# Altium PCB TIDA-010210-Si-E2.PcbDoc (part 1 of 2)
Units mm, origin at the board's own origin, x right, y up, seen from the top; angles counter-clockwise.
Board outline 75 x 60 mm, 2 copper layers (Top Layer, Bottom Layer), stack 1.565 mm thick; 77 components, 33 nets, 164 pads, 32 vias.
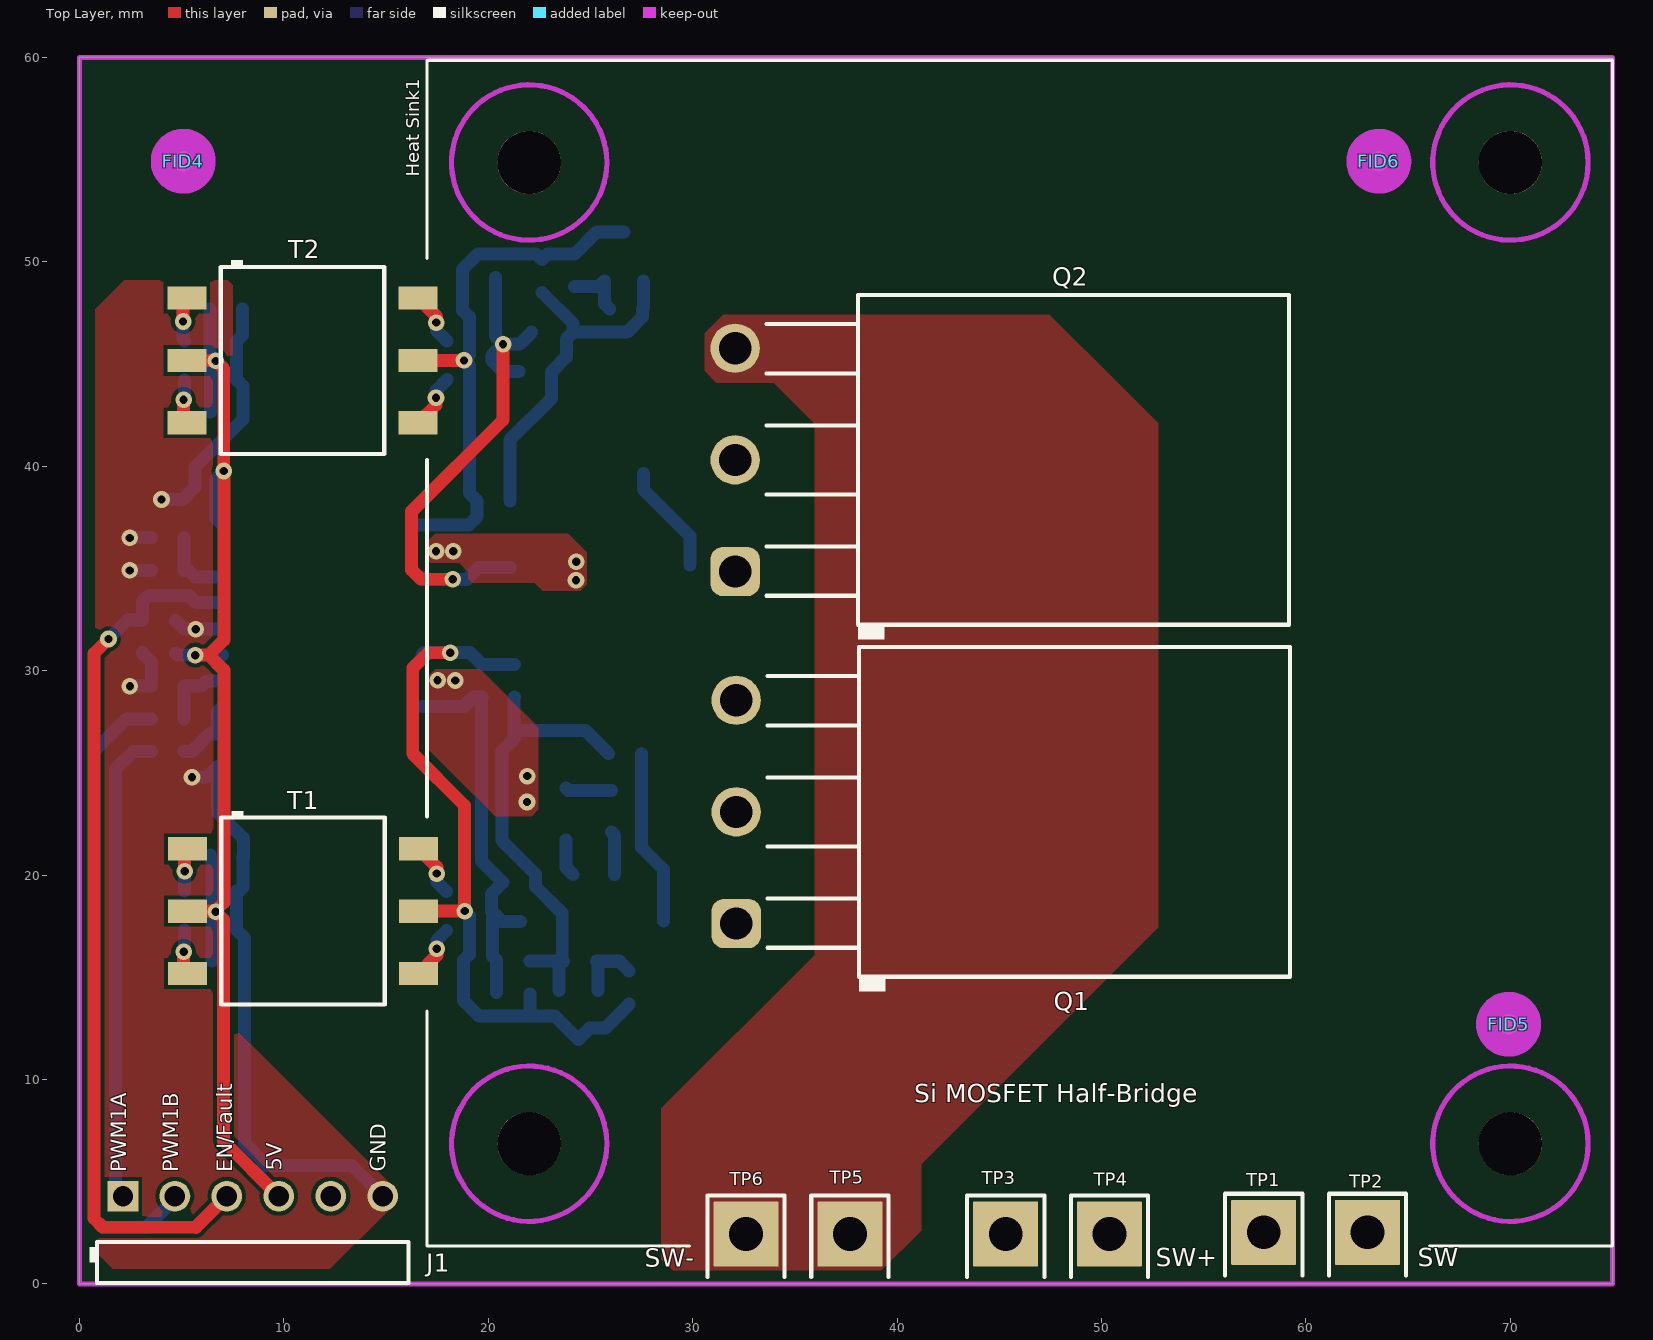
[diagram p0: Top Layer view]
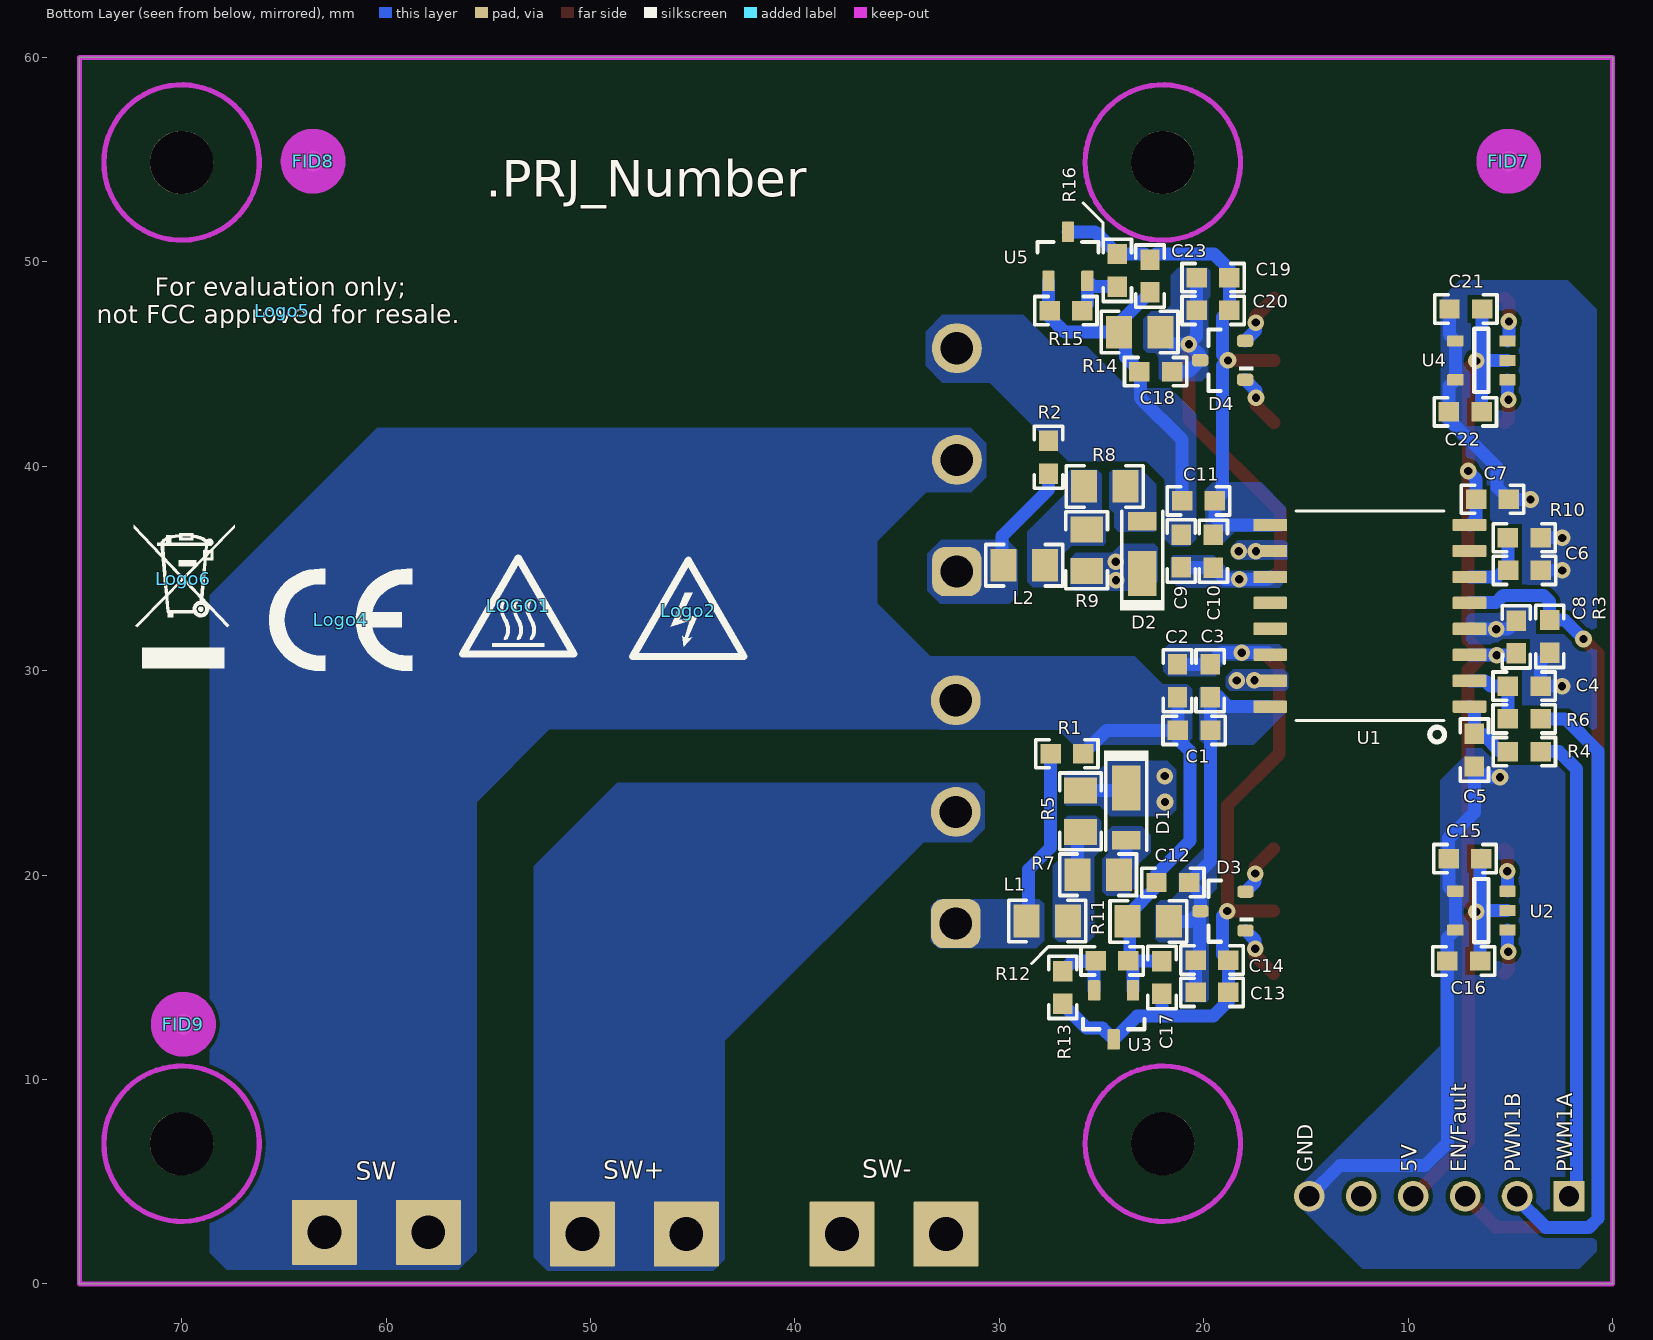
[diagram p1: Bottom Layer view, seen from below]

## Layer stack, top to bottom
Top Solder: solder mask 0.0102, Solder Resist, Dk 3.5
Top Layer: signal copper 0.0711
Dielectric 1: core 1.4224, FR-4 High Tg, Dk 4.2
Bottom Layer: signal copper 0.0711
Bottom Solder: solder mask 0.0102, Solder Resist, Dk 3.5

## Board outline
0,0 0,60 75,60 75,0

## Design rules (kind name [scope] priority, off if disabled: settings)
AcuteAngle [All] p1: minimum=4.50000000000000E+0001 checktracksonly=FALSE
AssemblyTestPointUsage [All] p1: valid=2
BoardOutlineClearance BoardOutlineClearance_MountingHoles [OnCopper and InComponentClass('Mounting Holes')] p1: gap=0.762 ignorepadtopadclearanceinfootprint=FALSE
BoardOutlineClearance BoardOutlineClearance_Poly [OnCopper and InPoly] p2: gap=0.635 ignorepadtopadclearanceinfootprint=FALSE
BoardOutlineClearance [OnCopper and Not InComponentClass('Logo') and not InComponentClass('FiducialMark') and not InRegion(1000,500,4000,800)] p3: gap=0.381 ignorepadtopadclearanceinfootprint=FALSE
Clearance Clearance_1 [All] p1: gap=0.2 ignorepadtopadclearanceinfootprint=FALSE except(0: Arc-SMDPad Arc-THPad Arc-Hole Track-Hole SMDPad-Hole THPad-Hole Via-Hole Fill-Hole Poly-Hole Region-Hole Text-Hole)
Clearance Clearance_Poly_poly [InPoly vs InPoly] p2: gap=0.508 ignorepadtopadclearanceinfootprint=FALSE except(0: Arc-Hole Track-Hole SMDPad-Hole THPad-Hole Via-Hole Fill-Hole Poly-Hole Region-Hole Text-Hole)
Clearance Clearance_Keepouts [((IsTrack Or IsArc) And Not InPoly) And IsFree and IsKeepOut vs ((IsTrack Or IsArc) And Not InPoly) And IsFree and IsKeepOut] p3: gap=0.508 ignorepadtopadclearanceinfootprint=FALSE except(0: Arc-Hole Track-Hole SMDPad-Hole THPad-Hole Via-Hole Fill-Hole Poly-Hole Region-Hole Text-Hole)
Clearance Clearance_Poly [InPolygon] p4: gap=0.381 ignorepadtopadclearanceinfootprint=FALSE except(0: Arc-Hole Track-Hole SMDPad-Hole THPad-Hole Via-Hole Fill-Hole Poly-Hole Region-Hole Text-Hole)
Clearance Clearance_2 [All] p5: gap=2.54 ignorepadtopadclearanceinfootprint=FALSE except(0: Arc-SMDPad Arc-THPad Arc-Hole Track-Hole SMDPad-Hole THPad-Hole Via-Hole Fill-Hole Poly-Hole Region-Hole Text-Hole; 0.254: Arc-Arc Arc-Track Arc-Via Arc-Fill Arc-Poly Arc-Region Arc-Text)
ComponentClearance ComponentClearance_MountingHoles_FiducialMarks [InComponentClass('Mounting Holes') vs InComponentClass('FiducialMark')] p1: gap=0.254 collisioncheckmode=3 verticalgap=0.254 showdistances=FALSE
ComponentClearance ComponentClearance_Shunt [InComponentClass('Header') vs InComponentClass('Shunt')] p2: gap=0 collisioncheckmode=3 verticalgap=0 showdistances=FALSE
ComponentClearance ComponentClearance_Logo [InComponentClass('Logo')] p3: gap=0.127 collisioncheckmode=3 verticalgap=0.127 showdistances=FALSE
ComponentClearance ComponentClearance_ScrewToNut [(HasFootprint('NY PMS 440 0025 PH')) vs (HasFootprint('Keystone_1902C'))] p4: gap=0.127 collisioncheckmode=3 verticalgap=0.254 showdistances=FALSE
ComponentClearance ComponentClearance_MountingHoles [InComponentClass('Mounting Holes')] p5: gap=6.35 collisioncheckmode=3 verticalgap=2540 showdistances=FALSE
ComponentClearance ComponentClearance_SmallPassives [HasFootprint('0201*') or HasFootprint('0402*') or HasFootprint('0508') or HasFootprint('0603*') or HasFootprint('0612') or HasFootprint('0805*') or HasFootprint('0815*') or HasFootprint('0830*') or HasFootprint('1206*') or HasFootprint('1210*') or HasFootprint('1808*') or HasFootprint('1812*') or HasFootprint('1825*') or HasFootprint('2010*') or HasFootprint('2220*') or HasFootprint('2225*') or HasFootprint('2512*') or HasFootprint('2728*') or HasFootprint('3518*') vs HasFootprint('0201*') or HasFootprint('0402*') or HasFootprint('0508') or HasFootprint('0603*') or HasFootprint('0612') or HasFootprint('0805*') or HasFootprint('0815*') or HasFootprint('0830*') or HasFootprint('1206*') or HasFootprint('1210*') or HasFootprint('1808*') or HasFootprint('1812*') or HasFootprint('1825*') or HasFootprint('2010*') or HasFootprint('2220*') or HasFootprint('2225*') or HasFootprint('2512*') or HasFootprint('2728*') or HasFootprint('3518*')] p6: gap=0.127 collisioncheckmode=3 verticalgap=0.127 showdistances=FALSE
ComponentClearance ComponentClearance_THtoSMT [IsThruComponent vs IsSMTComponent] p7: gap=0.127 collisioncheckmode=3 verticalgap=0.127 showdistances=FALSE
ComponentClearance ComponentClearance_THtoTH [IsThruComponent vs IsThruComponent] p8: gap=0 collisioncheckmode=3 verticalgap=0.254 showdistances=FALSE
ComponentClearance [All] p9: gap=0.025 collisioncheckmode=3 verticalgap=0.025 showdistances=FALSE
DiffPairsRouting [All] p1: maxlimit=2.54 minlimit=0.254 mostfreqgap=0.254 toplayer_minwidth=0.381 toplayer_maxwidth=0.381 toplayer_prefwidth=0.381 bottomlayer_minwidth=0.381 bottomlayer_maxwidth=0.381 bottomlayer_prefwidth=0.381 maxuncoupledlength=25.4
FabricationTestPointUsage TestPointUsage [All] p1: valid=2 allowmultiple=FALSE
FabricationTestpoint Testpoint [All] p1: side=3 testpointundercomponent=TRUE minsize=1.016 maxsize=2.54 preferedsize=1.524 minholesize=0 maxholesize=1.016 preferedholesize=0.813 testpointgrid=0.025 allowsidetop=TRUE allowsidebottom=TRUE usegrid=TRUE gridtolerance=0
FanoutControl Fanout_LCC [IsLCC] p1: bgadir=Out bgaviamode=Centered fanoutstyle=Auto fanoutdirection=Alternating viagrid=0.025 // Fanout_LCC (Default Rule)
FanoutControl Fanout_BGA [IsBGA] p2: bgadir=Out bgaviamode=Centered fanoutstyle=Auto fanoutdirection=Alternating viagrid=0.025 // Fanout_BGA (Default Rule)
FanoutControl Fanout_Default [All] p4: bgadir=Out bgaviamode=Centered fanoutstyle=Auto fanoutdirection=Alternating viagrid=0.025 // Fanout_Default (Default Rule)
FanoutControl Fanout_Small [(CompPinCount < 5)] p5: bgadir=Out bgaviamode=Centered fanoutstyle=Auto fanoutdirection=OutThenIn viagrid=0.025 // Fanout_Small (Default Rule)
Height [All] p1: minheight=0 maxheight=38.1 prefheight=12.7
HoleSize [All] p1: absolutevalues=TRUE maxlimit=6.375 minlimit=0.2 maxpercent=80.000 minpercent=20.000
MinimumAnnularRing MinimumAnnularRing_ThermalPadVias [IsVia and InAnyComponent] p1: minimumring=0.102
MinimumAnnularRing [All] p2: minimumring=0.102
MinimumSolderMaskSliver MinimumSolderMaskSliver_Logo [InComponentClass('Logo') vs InComponentClass('Logo')] p1: minsoldermaskwidth=0.018
MinimumSolderMaskSliver [All] p2: minsoldermaskwidth=0.1
PlaneClearance [All] p1: clearance=0.254
PlaneConnect [All] p1: planeconnectstyle=Relief reliefexpansion=0.254 reliefentries=4 reliefconductorwidth=0.254 reliefairgap=0.254
PolygonConnect PolygonConnectThermalVia [isvia] p1: connectstyle=Direct reliefconductorwidth=0.254 reliefentries=4 polygonreliefangle="90 Angle" airgapwidth=0.254
PolygonConnect PolygonConnectThermalPad [((ObjectKind = 'Pad') And (((Name Like 'U*') or (Name Like 'D*')) and (InComponentClass('TIDA-00183_pg-4_Driver') or InComponentClass('TIDA-00183_pg-5_OP_Connector')))) or ((ObjectKind = 'Pad') And (Name like 'U61*'))] p2: connectstyle=Direct reliefconductorwidth=0.254 reliefentries=4 polygonreliefangle="90 Angle" airgapwidth=0.254
PolygonConnect [All] p3: connectstyle=Direct reliefconductorwidth=0.254 reliefentries=4 polygonreliefangle="90 Angle" airgapwidth=0.127
RoutingVias ThermalPadVias [IsVia and InAnyComponent] p1: holewidth=0.2 width=0.5 viastyle="Through Hole" minholewidth=0.2 minwidth=0.5 maxholewidth=0.33 maxwidth=0.6
RoutingVias [All] p2: holewidth=0.406 width=0.864 viastyle="Through Hole" minholewidth=0.203 minwidth=0.508 maxholewidth=1.016 maxwidth=1.651
SilkToBoardRegionClearance [Not ((IsComment or IsDesignator) And (Hide <> 'False')) and not InRegion(1000,500,4000,800)] p1:
SilkToSilkClearance SilkToSilkClearance_Pb-FreeLogo [(HasFootprint('Pb-Free_Overlay_Medium') OR HasFootprint('Pb-Free_Overlay_Small')) vs (HasFootprint('Pb-Free_Overlay_Medium') OR HasFootprint('Pb-Free_Overlay_Small'))] p1: silktosilkclearance=0
SilkToSilkClearance [All] p2: silktosilkclearance=0.102
SilkToSolderMaskClearance SilkToComponentPadClearance [IsPad and InAnycomponent] p1: minsilkscreentomaskgap=0.127 clearancetoexposedcopper=TRUE
SilkToSolderMaskClearance "Silk to Solder Mask Opening" [All] p2: minsilkscreentomaskgap=0.102 clearancetoexposedcopper=FALSE
SolderMaskExpansion [All] p1: expansion=0.05 istentingtop=FALSE
Width [All] p1: maxlimit=2.54 minlimit=0.381 preferedwidth=0.635 toplayer_prefwidth=0.63 minimp=50.000000 maximp=50.000000 favimp=50.000000 checkconnectedcopper=TRUE
13 further rules are at their usual default settings.

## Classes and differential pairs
component class Header: J1
component class FiducialMark: FID4 FID5 FID6 FID7 FID8 FID9
component class "EVM Hardware-Pg6": FID4 FID5 FID6 FID7 FID8 FID9 J4 LOGO1 Logo2 Logo4 Logo5 Logo6 TP11 TP12 TP13 TP14 TP15 TP17 ZZ1 ZZ2 ZZ3 ZZ4
component class "Bias Power Supply-Pg5": C12 C13 C14 C15 C16 C17 C18 C19 C20 C21 C22 C23 C38 D3 D4 R11 R12 R13 R14 R15 R16 T1 T2 U2 U3 U4 U5
component class "Gate Driver Circuit-Pg4": C1 C2 C3 C4 C5 C6 C7 C8 C9 C10 C11 D1 D2 J1 L1 L2 R3 R4 R5 R6 R7 R8 R9 R10 U1
component class AssemblyNote: ZZ1 ZZ2 ZZ3 ZZ4
component class "Power Stage-Pg3": "Heat Sink1" Q1 Q2 R1 R2 TP1 TP2 TP3 TP4 TP5 TP6

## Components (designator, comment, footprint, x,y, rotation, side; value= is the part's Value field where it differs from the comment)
C1 "C1608X5R1V475K080AC" 0603 20.472,27.076 r0 bottom value=4.7uF
C2 "C1608X5R1V475K080AC" 0603 21.284,29.504 r270 bottom value=4.7uF
C3 "C1608X7R1H104K080AA" 0603 19.687,29.504 r90 bottom value=0.1uF
C4 "CL10B101KB8NNNC" 0603 4.327,29.238 r180 bottom value=100pF
C5 "CL10B101KB8NNNC" 0603 6.764,26.111 r270 bottom value=100pF
C6 "C0603X222K5RACTU" 0603 4.314,34.902 r180 bottom value=2200pF
C7 "C1608X7R1H104K080AA" 0603 5.877,38.382 r180 bottom value=0.1uF
C8 "C1608X7R1H104K080AA" 0603 4.711,31.651 r90 bottom value=0.1uF
C9 "C1608X5R1V475K080AC" 0603 21.1,35.854 r90 bottom value=4.7uF
C10 "C1608X7R1H104K080AA" 0603 19.534,35.842 r90 bottom value=0.1uF
C11 "C1608X5R1V475K080AC" 0603 20.259,38.305 r0 bottom value=4.7uF
C12 "C1608X7R1H104K080AA" 0603 21.514,19.634 r0 bottom value=0.1uF
C13 "C1608X5R1V475K080AC" 0603 19.601,14.26 r180 bottom value=4.7uF
C14 "C1608X5R1V475K080AC" 0603 19.601,15.84 r180 bottom value=4.7uF
C15 "GRM188Z71A106MA73D" 0603 7.219,20.801 r0 bottom value=10uF
C16 "GRM188Z71A106MA73D" 0603 7.283,15.797 r0 bottom value=10uF
C17 "C1608X7R1H104K080AA" 0603 22.047,14.986 r270 bottom value=0.1uF
C18 "C1608X7R1H104K080AA" 0603 22.352,44.628 r0 bottom value=0.1uF
C19 "C1608X5R1V475K080AC" 0603 19.545,49.225 r180 bottom value=4.7uF
C20 "C1608X5R1V475K080AC" 0603 19.545,47.625 r180 bottom value=4.7uF
C21 "GRM188Z71A106MA73D" 0603 7.181,47.691 r0 bottom value=10uF
C22 "GRM188Z71A106MA73D" 0603 7.206,42.661 r0 bottom value=10uF
C23 "C1608X7R1H104K080AA" 0603 22.631,49.301 r90 bottom value=0.1uF
D1 "DFLS240-7" PowerDI123 23.794,22.987 r270 bottom value=40V
D2 "DFLS240-7" PowerDI123 23.012,36.038 r90 bottom value=40V
D3 "BAV70-E3-08" SOT-23L 19.061,18.235 r0 bottom value=70V
D4 "BAV70-E3-08" SOT-23L 19.078,45.183 r0 bottom value=70V
FID4 "Fiducial" Fiducial10-30 5.08,54.92 r0 top
FID5 "Fiducial" Fiducial10-30 69.92,12.7 r0 top
FID6 "Fiducial" Fiducial10-30 63.57,54.92 r0 top
FID7 "Fiducial" Fiducial10-30 5.08,54.92 r180 bottom
FID8 "Fiducial" Fiducial10-30 63.57,54.92 r180 bottom
FID9 "Fiducial" Fiducial10-30 69.92,12.7 r180 bottom
"Heat Sink1" "SKV585811-AL" SKV585811_AL 46.005,30.858 r0 top locked
J1 "90121-0766" Molex_90121-0766 8.484,4.293 r0 top locked
L1 "782853121" 0805_HV 27.661,17.755 r0 bottom value="120 ohm"
L2 "782853121" 0805_HV 28.778,35.154 r0 bottom value="120 ohm"
LOGO1 "CAUTION HOT SURFACE" IEC_HotSurface_Small 53.54,33.17 r180 bottom
Logo2 "DANGER HIGH VOLTAGE" IEC_HighVoltage_Small 45.212,32.929 r180 bottom (schematic designator LOGO2)
Logo4 "CE Mark" CE_Mark_5mm 62.23,32.487 r180 bottom
Logo5 "FCC disclaimer" FCC_disclaimer_stacked 65.075,47.6 r0 bottom
Logo6 "WEEE logo" WEEE_Minimum 69.926,34.493 r180 bottom
Q1 "FCH040N65S3-F155" TO-247_HORIZONTAL_DOWN 32.131,23.089 r90 top locked value=650V
Q2 "FCH040N65S3-F155" TO-247_HORIZONTAL_DOWN 32.08,40.31 r90 top locked value=650V
R1 "CRCW060310K0JNEA" 0603 26.695,25.933 r0 bottom value=10k
R2 "CRCW060310K0JNEA" 0603 27.595,40.437 r270 bottom value=10k
R3 "RCA06031K00JNEA" 0603 3.076,31.676 r90 bottom value=1.0k
R4 "CRCW0603100RFKEA" 0603 4.321,26.037 r0 bottom value=100
R5 "CRCW080522R1FKEA" 0805_HV 26.03,23.114 r270 bottom value=22.1
R6 "CRCW0603100RFKEA" 0603 4.327,27.643 r0 bottom value=100
R7 "CRCW080522R1FKEA" 0805_HV 25.172,20.015 r0 bottom value=22.1
R8 "CRCW080522R1FKEA" 0805_HV 24.841,39.014 r0 bottom value=22.1
R9 "CRCW080522R1FKEA" 0805_HV 25.729,35.89 r90 bottom value=22.1
R10 "RT0603BRD0710KL" 0603 4.324,36.502 r0 bottom value=10.0k
R11 "CRCW08054K70JNEA" 0805_HV 22.708,17.735 r180 bottom value=4.7k
R12 "RT0603DRE074K99L" 0603 24.486,15.799 r180 bottom value=4.99k
R13 "RT0603DRE074K99L" 0603 26.899,14.503 r90 bottom value=4.99k
R14 "CRCW08054K70JNEA" 0805_HV 23.139,46.558 r180 bottom value=4.7k
R15 "RT0603DRE074K99L" 0603 26.745,47.614 r0 bottom value=4.99k
R16 "RT0603DRE074K99L" 0603 24.232,49.581 r270 bottom value=4.99k
T1 "750342879" Wurth_750342879 10.941,18.235 r0 top value=50uH
T2 "750342879" Wurth_750342879 10.914,45.176 r0 top value=50uH
TP1 "3620-2-32-15-00-00-08-0" Mill-Max_3620-2-32-xx-00-00-08-0 57.935,0 r0 top locked
TP2 "3620-2-32-15-00-00-08-0" Mill-Max_3620-2-32-xx-00-00-08-0 63.015,0 r0 top locked
TP3 "3620-2-32-15-00-00-08-0" Mill-Max_3620-2-32-xx-00-00-08-0 45.314,-0.082 r0 top locked
TP4 "3620-2-32-15-00-00-08-0" Mill-Max_3620-2-32-xx-00-00-08-0 50.394,-0.082 r0 top locked
TP5 "3620-2-32-15-00-00-08-0" Mill-Max_3620-2-32-xx-00-00-08-0 37.694,-0.082 r0 top locked
TP6 "3620-2-32-15-00-00-08-0" Mill-Max_3620-2-32-xx-00-00-08-0 32.614,-0.082 r0 top locked
U1 "UCC21540DWR" DW0016B_HV 11.876,32.679 r0 bottom
U2 "SN6501QDBVRQ1" DBV0005A_L 6.419,18.261 r0 bottom
U3 "ATL431LIAQDBZR" DBZ0003A_N 24.409,13.157 r270 bottom
U4 "SN6501QDBVRQ1" DBV0005A_L 6.419,45.176 r0 bottom
U5 "ATL431LIAQDBZR" DBZ0003A_N 26.645,50.267 r90 bottom
ZZ1 "This Assembly Note is for PCB labels only" AssemblyNoteLabel 5.186,73.84 r0 top
ZZ2 "This Assembly Note will show in the PcbDoc and associated outputs" AssemblyNote 5.186,71.074 r0 top
ZZ3 "This Assembly Note will show in the PcbDoc and associated outputs" AssemblyNote 5.186,68.825 r0 top
ZZ4 "This Assembly Note will show in the PcbDoc and associated outputs" AssemblyNote 5.186,66.575 r0 top

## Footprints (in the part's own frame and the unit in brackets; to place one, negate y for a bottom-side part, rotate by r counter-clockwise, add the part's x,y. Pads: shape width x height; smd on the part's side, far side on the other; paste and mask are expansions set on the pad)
0603 [mm] "0603 from SM-752 data"
  rect 1x0.95 smd: 1(-0.8,0) 2(0.8,0)
  silkscreen extent -1.52,-0.69 1.52,0.69, body extent -0.87,-0.47 0.87,0.47, height 1
0805_HV [mil] "0805 with 30mil clearance between pads"
  rect 50x63 smd: 1(-40,0) 2(40,0)
  silkscreen extent -74,-40 74,40, body extent -43,-29 43,29, height 57
AssemblyNote [mm] "Assembly Note"
AssemblyNoteLabel [mm] "Assembly Note for PCB Labels"
CE_Mark_5mm [mm] "Minimum text height for CE Mark"
  silkscreen extent -3.5,-2.5 3.5,2.5
DBV0005A_L [mm] "SOT23, 5-Leads, Body 2.9x1.6mm, Pitch 0.95mm, Lead Span 2.8mm, IPC High Density"
  rrect18% 0.8x0.55 smd: 1(-1.275,0.95) 2(-1.275,0) 3(-1.275,-0.95) 4(1.275,-0.95) 5(1.275,0.95)
  silkscreen extent -0.35,-1.55 0.35,1.55, body extent -1.42,-1.46 1.42,1.46, height 1.09
DBZ0003A_N [mm] "SOT23, 3-Leads, Body 2.9x1.3mm, Pitch 0.95mm, Lead Span 2.4mm, IPC Medium Density"
  rrect17% 1x0.6 smd: 1(-1.2,0.95) 2(-1.2,-0.95) 3(1.2,0)
  silkscreen extent 0.2,-1.5 0.7,1.5, body extent -1.26,-1.46 1.26,1.46, height 0.98
DW0016B_HV [mm] "SOIC-16, HV/isolation option"
  rrect17% 1.65x0.6 smd: 1(-4.875,4.445) 2(-4.875,3.175) 3(-4.875,1.905) 4(-4.875,0.635) 5(-4.875,-0.635) 6(-4.875,-1.905) 7(-4.875,-3.175) 8(-4.875,-4.445) 9(4.875,-4.445) 10(4.875,-3.175) 11(4.875,-1.905) 12(4.875,-0.635) 13(4.875,0.635) 14(4.875,1.905) 15(4.875,3.175) 16(4.875,4.445)
  body extent -5.17,-5.15 5.17,5.15, height 2.59
FCC_disclaimer_stacked [mm]
Fiducial10-30 [mm]
  round 1 smd mask+1: 1(0,0)
  Top Layer keep-out circle w1.678: c0,0 r0.75
IEC_HighVoltage_Small [mm]
  silkscreen extent -2.72,-2.24 2.72,2.47
IEC_HotSurface_Small [mm]
  silkscreen extent -2.72,-2.36 2.72,2.35
Mill-Max_3620-2-32-xx-00-00-08-0 [mm] "PCB Pin, 0.04\" DIA, R/A, Edge-Mount"
  rrect3% 3.18x3.18 hole 1.65: 1(0,2.52)
  silkscreen extent -1.89,0.41 1.89,4.41, body extent -1.59,-5.06 1.59,4.11, height 0.65
Molex_90121-0766 [mm] "Header, 2.54mm, 6x1, R/A, TH"
  rect 1.5x1.5 hole 1: 1(-6.35,0)
  round 1.5 hole 1: 2(-3.81,0) 3(-1.27,0) 4(1.27,0) 5(3.81,0) 6(6.35,0)
  silkscreen extent -8,-4.25 7.62,-2.25, body extent -7.62,-11 7.62,0.32, height 3.63
PowerDI123 [mm] "Diodes Inc recommended land pattern, document number DS30628 Rev. 6-2"
  rect 2.2x1.4 smd: 1(-1.275,0)
  rect 0.9x1.4 smd: 2(1.275,0)
  silkscreen extent -3.1,-1.09 1.76,1.09, body extent -2.37,-0.96 1.53,0.97, height 1
SKV585811_AL [mm] "HeatSink"
  round 3.1 hole 3.1 unplated mask+0.178: 1(-24,-24) 2(24,-24) 3(24,24) 4(-24,24)
  silkscreen extent -29,-29 29,29, body extent -29,-29 29,29, height 21
SOT-23L [mm] "SOT23, 3-Leads, Body 2.9x1.3mm, Pitch 0.95mm, Lead Span 2.5mm, IPC High Density"
  rrect50% 0.8x0.6 smd: 1(-1.1,0.95) 2(-1.1,-0.95) 3(1.1,0)
  silkscreen extent -1.5,-1.5 0.7,1.5, body extent -1.16,-1.45 1.21,1.45, height 1
TO-247_HORIZONTAL_DOWN [mil] "TH, 3-Leads, Body 16.13x 21.1mm, Pitch 5.461mm"
  rrect50% 95x95 hole 62: 1(-215,0)
  round 95 / inner round 74.8 / far side round 96 hole 62: 2(0,0) 3(215,0)
  silkscreen extent -346,-1067 318,-60, body extent -318,-1067 318,13, height 205
WEEE_Minimum [mm] "WEEElie bin"
  silkscreen extent -2.42,-4.38 2.52,2.65
Wurth_750342879 [mm] "SMD, 6-Leads, Body 9.14x8mm, Pitch 3.05mm"
  rect 1.9x1.14 smd: 1(-5.655,3.05) 2(-5.655,0) 3(-5.655,-3.05) 4(5.655,-3.05) 5(5.655,0) 6(5.655,3.05)
  silkscreen extent -4,-4.57 4,4.9, body extent -6.35,-4.57 6.35,4.57, height 7.83

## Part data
C1 C2 C9 C11 C13 C14 C19 C20: library part CMP-0007022-5, "CAP, CERM, 4.7 uF, 35 V, +/- 10%, X5R, 0603", Cap_Case=0603, Manufacturer=TDK, Supplier Part Number 1=445-9064-1-ND, TempCo=X5R, Tolerance_%=10%, Value1="0.003728 ohm", Value2=35V, ValueDisplayed=4.7uF
C3 C7 C8 C10 C12 C17 C18 C23: library part CMP-0007044-5, "CAP, CERM, 0.1 uF, 50 V, +/- 10%, X7R, 0603", Cap_Case=0603, Manufacturer=TDK, Supplier Part Number 1=445-1314-1-ND, TempCo=X7R, Tolerance_%=10%, Value1="0.0296 ohm", Value2=50V, ValueDisplayed=0.1uF
C4 C5: library part CMP-0083857-1, "CAP, CERM, 100 pF, 50 V,+/- 10%, X7R, 0603", Cap_Case=0603, Manufacturer="Samsung Electro-Mechanics", TempCo=X7R, Tolerance_%=10%, Value2=50V, ValueDisplayed=100pF
C6: library part CMP-0006983-4, "CAP, CERM, 2200 pF, 50 V, +/- 10%, X7R, 0603", Cap_Case=0603, Manufacturer=Kemet, Supplier Part Number 1=399-5341-1-ND, TempCo=X7R, Tolerance_%=10%, Value1=Unknown, Value2=50V, ValueDisplayed=2200pF
C15 C16 C21 C22: library part CMP-0007497-5, "CAP, CERM, 10 uF, 10 V, +/- 20%, X7R, 0603", Cap_Case=0603, Manufacturer=MuRata, Supplier Part Number 1=81-GRM188Z71A106MA3D, TempCo=X7R, Tolerance_%=20%, Value1=Unknown, Value2=10V, ValueDisplayed=10uF
D1 D2: library part CMP-0028850-2, "Diode, Schottky, 40 V, 2 A, AEC-Q101, PowerDI123", Manufacturer="Diodes Inc.", Value1=2A, Value2=0.5V
D3 D4: library part CMP-0077061-2, "Diode, Switching, 70 V, 0.25 A, AEC-Q101, SOT-23", Manufacturer=Vishay-Semiconductor, Value1=0.25A, Value2=1.25V
FID4 FID5 FID6 FID7 FID8 FID9: library part CMP-0077181-1, "Fiducial mark.  There is nothing to buy or mount.", Manufacturer=N/A
"Heat Sink1": library part 3-101004U, "ALUMINUM HEATSINK 57.9X59X11MM", Manufacturer=Wakefield-Vette, Supplier Part Number 1=345-2031-ND
J1: library part CMP-0055334-1, "Header, 2.54mm, 6x1, Gold, R/A, TH", Color=Black, Current_A=3A, Manufacturer=Molex, Supplier Part Number 1=WM8112-ND, Voltage_V=350V
L1 L2: library part CMP-0003294-1, "Ferrite Bead, 120 ohm @ 100 MHz, 2.5 A, 0805", Manufacturer="Wurth Elektronik", Supplier Part Number 1=732-6710-1-ND, Value1="0.035 ohm", Value2=2.5A, ValueDisplayed="120 ohm"
LOGO1: library part CMP-0074837-1, "IEC 61010-1 Hot Surface Warning"
Logo2: library part CMP-0074835-1, "IEC 61010-1 High Voltage Warning"
Logo4: library part CMP-0074844-1
Logo5: library part CMP-0074847-1, "FCC_disclaimer"
Logo6: library part CMP-0074769-1
Q1 Q2: library part IPW65R070C6FKSA1, "MOSFET N-CH 650V 65A TO247-3", Alternate Manufacturer=None, Manufacturer="ON Semiconductor", Supplier Part Number 1=FCH040N65S3-F155-ND, Value1="? ohm", Value2="170 nC"
R1 R2: library part CMP-0025701-4, "RES, 10 k, 5%, 0.1 W, AEC-Q200 Grade 0, 0603", Manufacturer=Vishay-Dale, Power_W=100mW, Supplier Part Number 1=541-10KGCT-ND, TempCo="200 ppm/C", Tolerance_%=5%, Value2=0.1W, Value_Code=10k0, ValueDisplayed=10k
R3: library part CMP-0025946-3, "RES, 1.0 k, 5%, 0.1 W, AEC-Q200 Grade 0, 0603", Manufacturer=Vishay-Dale, Power_W=100mW, Supplier Part Number 1=541-2213-1-ND, TempCo="200 ppm/C", Tolerance_%=5%, Value2=0.1W, Value_Code=1k00, ValueDisplayed=10.0k
R4 R6: "RES, 100, 1%, 0.1 W, 0603", Manufacturer=Vishay-Dale, Power_W=0.1, Supplier Part Number 1=541-100HCT-ND, TempCo="100 ppm/C", Tolerance_%=1, Value1=1%, Value2=0.1W, Value_Code=100R, ValueDisplayed=100
R5 R7 R8 R9: library part CMP-0021060-3, "RES, 22.1, 1%, 0.125 W, AEC-Q200 Grade 0, 0805", Manufacturer=Vishay-Dale, Power_W=125mW, Supplier Part Number 1=541-22.1CCT-ND, TempCo="100 ppm/C", Tolerance_%=1%, Value2=0.125W, Value_Code=22R1, ValueDisplayed=22.1
R10: library part CMP-0023653-3, "RES, 10.0 k, 0.1%, 0.1 W, 0603", Manufacturer="Yageo America", Power_W=100mW, TempCo="25 ppm/C", Tolerance_%=0.1%, Value2=0.1W, Value_Code=10k0, ValueDisplayed=10.0k
R11 R14: library part CMP-0020559-3, "RES, 4.7 k, 5%, 0.125 W, AEC-Q200 Grade 0, 0805", Manufacturer=Vishay-Dale, Power_W=125mW, Supplier Part Number 1=541-4.7KACT-ND, TempCo="200 ppm/C", Tolerance_%=5%, Value2=0.125W, Value_Code=4k70, ValueDisplayed=4.7k
R12 R13 R15 R16: library part CMP-0025353-3, "RES, 4.99 k, 0.5%, 0.1 W, 0603", Manufacturer="Yageo America", Power_W=100mW, TempCo="50 ppm/C", Tolerance_%=0.5%, Value2=0.1W, Value_Code=4k99, ValueDisplayed=4.99k
T1 T2: library part CMP-0030690-1, "Transformer, 50 uH, SMT", Manufacturer="Wurth Elektronik", ValueDisplayed=50uH
TP1 TP2 TP3 TP4 TP5 TP6: library part CMP-0055044-1, Manufacturer=Mill-Max, Supplier Part Number 1=ED1278-ND
U1: library part CMP-0083795-2, "Isolated Dual-Channel Gate Driver, DW0016B (SOIC-16)", Alternate Manufacturer="Texas Instruments", Alternate PartNumber=UCC21540DW, PartNumber=UCC21541DWR
U2 U4: library part CMP-0076093-1, "Automotive Low-Noise 350 mA, 410 kHz Transformer Driver, DBV0005A (SOT-23-5)", Alternate Manufacturer="Texas Instruments"
U3 U5: library part CMP-0084733-1, "High Bandwidth Low-Iq Programmable Shunt Regulator, DBZ0003A (SOT-23-3)", Alternate Manufacturer="Texas Instruments"
ZZ1: library part AssemblyNoteLabel
ZZ2 ZZ3 ZZ4: library part AssemblyNote

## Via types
v1: diameter 0.813, hole 0.406, Top Layer to Bottom Layer, tented both sides, 31 vias
v2: diameter 0.813, hole 0.406, Top Layer to Bottom Layer, 1 vias

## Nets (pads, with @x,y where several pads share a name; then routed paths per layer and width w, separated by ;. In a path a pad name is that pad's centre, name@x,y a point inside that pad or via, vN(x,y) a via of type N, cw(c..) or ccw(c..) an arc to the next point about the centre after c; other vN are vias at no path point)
5V: C7.1 C8.1 C15.1 C16.1 C21.1 C22.1 J1.4 T1.2 T2.2 U1.3 U1.8 U2.2 U4.2 | length 64.2
  Top Layer w0.63: T2.2@5.259,45.176 6.647,45.176 v1(6.673,45.151) 7.061,44.762 v1(7.061,39.763) ; T1.2@5.286,18.235 v1@6.635,18.235
  Top Layer w0.635: v1(5.664,30.759) 6.325,30.759 6.328,30.762 ; v1@6.635,18.235 7.054,18.654 7.065,18.664 7.065,30.025 6.328,30.762 ; v1(6.673,18.197) 7.054,17.816 7.054,6.992 J1.4@9.754,4.293 ; v1(7.061,39.763) 7.064,39.76 7.064,31.498 6.328,30.762
  Bottom Layer w0.635: C8.1@4.711,30.851 4.788,30.774 U1.3@7.001,30.774 ; U2.2@5.144,18.261 6.42,18.261 v1@6.483,18.197 ; U4.2@5.144,45.176 v1@6.355,45.176 ; v1@6.381,45.176 C21.1@6.381,47.691 ; C15.1@6.407,20.801 C15.1@6.407,20.978 ; C22.1@6.406,42.661 6.406,44.833 ; C15.1@6.419,20.801 6.483,20.736 v1@6.483,18.197 ; C16.1@6.483,15.797 v1@6.483,18.197 ; U1.8@7.001,37.124 6.677,37.449 C7.1@6.677,38.382 6.677,39.379 v1(7.061,39.763)
+12Va: C1.1 C3.1 C12.1 C13.1 C14.1 D3.3 R11.2 U1.16 | length 19.9
  Bottom Layer w0.635: U1.16@16.751,28.234 18.806,28.234 19.276,28.704 C3.1@19.687,28.704 19.672,28.69 C1.1@19.672,27.076 19.672,20.676 C12.1@20.714,19.634 20.161,19.081 D3.3@20.161,18.235 D3.3@20.218,18.177 ; C13.1@20.401,14.26 C14.1@20.401,15.84 20.218,16.023 D3.3@20.218,18.177 ; R11.2@21.59,17.735 20.661,17.735 D3.3@20.218,18.177
+12Vb: C9.1 C10.1 C18.1 C19.1 C20.1 D4.3 R14.2 U1.11 | length 27.4
  Top Layer w0.63: v1(18.261,34.468) 16.713,34.468 16.256,34.925 16.256,37.794 20.726,42.265 v1(20.726,45.974)
  Bottom Layer w0.635: U1.11@16.751,34.584 16.868,34.468 v1(18.261,34.468) 18.96,34.468 C10.1@19.534,35.042 19.546,35.054 C9.1@21.1,35.054 ; C19.1@20.345,49.225 C20.1@20.345,47.625 20.345,46.355 v1(20.726,45.974) ; C18.1@21.501,44.628 20.733,44.628 D4.3@20.178,45.183 20.178,45.425 v1(20.726,45.974) ; R14.2@22.123,46.558 21.539,45.974 v1(20.726,45.974)
-5Va: C2.1 C3.2 C13.2 C14.2 C17.2 R13.1 T1.5 U1.14 U3.3 | length 37.4
  Top Layer w0.63: T1.5@16.596,18.235 18.845,18.235 18.845,23.401 16.307,25.939 16.307,30.124 17.058,30.876 v1(18.139,30.876)
  Bottom Layer w0.635: U1.14@16.751,30.774 16.853,30.876 v1(18.139,30.876) 19.115,30.876 C3.2@19.687,30.304 C2.1@21.284,30.304 ; v2(18.847,18.237) 19.075,18.009 19.075,16.114 C14.2@18.801,15.84 C13.2@18.801,14.26 18.801,13.838 19.533,13.106 22.047,13.106 ; C17.2@22.047,14.186 22.047,13.106 ; R13.1@26.899,13.703 26.899,13.678 25.73,12.51 24.962,12.51 U3.3@24.409,11.957 23.26,13.106 22.047,13.106
-5Vb: C10.2 C11.1 C19.2 C20.2 C23.2 R16.1 T2.5 U1.9 U5.3 | length 26.8
  Top Layer w0.63: T2.5@16.569,45.176 v1(18.817,45.176)
  Bottom Layer w0.635: U1.9@16.596,37.124 U1.9@16.751,37.124 19.051,37.124 19.459,37.532 C11.1@19.459,38.305 19.075,38.689 19.075,44.917 v1(18.817,45.176) 19.075,45.435 19.075,47.295 C20.2@18.745,47.625 C19.2@18.745,49.225 18.745,49.632 19.506,50.392 22.341,50.392 C23.2@22.631,50.101 22.911,50.381 R16.1@24.232,50.381 25.317,51.467 U5.3@26.645,51.467
G1H_P: L1.2 Q1.1 R1.2 | length 8.6
  Bottom Layer w0.635: R1.2@27.495,25.933 27.495,21.349 28.575,20.269 L1.2@28.575,17.755
G1L_P: L2.2 Q2.1 R2.2 | length 5.4
  Bottom Layer w0.635: R2.2@27.595,39.637 27.595,38.852 29.87,36.576 L2.2@29.87,35.179
GND: C4.2 C5.2 C6.2 C7.2 C8.2 C15.2 C16.2 C21.2 C22.2 J1.6 R3.1 R10.1 U1.4 U2.4 U2.5 U4.4 U4.5 | length 48
  Bottom Layer w0.635: v1(2.467,34.902) 2.476,34.911 3.524,34.911 C6.2@3.514,34.902 ; v1(2.467,36.493) 2.476,36.502 R10.1@3.524,36.502 ; v1(2.472,29.238) C4.2@3.527,29.238 3.527,30.401 3.076,30.851 R3.1@3.076,30.876 ; v1(4.02,38.372) 4.029,38.382 C7.2@5.077,38.382 5.659,38.964 5.659,39.949 8.006,42.296 C22.2@8.006,42.661 8.006,43.914 U4.5@7.694,44.226 U4.4@7.694,46.126 7.981,46.413 C21.2@7.981,47.691 ; C8.2@4.711,32.451 5.13,32.032 v1(5.693,32.032) 5.77,32.032 5.782,32.044 U1.4@7.001,32.044 ; v1(5.507,24.79) 6.243,24.79 C5.2@6.764,25.311 6.764,23.056 8.019,21.801 C15.2@8.019,20.801 C15.2@8.007,20.813 ; C15.2@7.986,20.833 C15.2@8.007,20.813 ; J1.6@14.834,4.293 13.335,5.791 9.174,5.791 8.083,6.883 C16.2@8.083,15.797 8.083,16.922 U2.5@7.694,17.311 U2.4@7.694,19.211 7.827,19.211 8.007,19.391 C15.2@8.007,20.813
NetC4_1: C4.1 R6.2 U1.2 | length 3.6
  Bottom Layer w0.635: R6.2@5.127,27.643 C4.1@5.127,29.238 5.972,29.238 6.239,29.504 U1.2@7.001,29.504
NetC5_1: C5.1 R4.2 U1.1 | length 3.4
  Bottom Layer w0.635: R4.2@5.121,26.037 5.491,26.037 6.365,26.911 C5.1@6.764,26.911 6.764,27.997 U1.1@7.001,28.234
NetC6_1: C6.1 R10.2 U1.6 | length 3.6
  Bottom Layer w0.635: R10.2@5.124,36.502 5.114,36.493 C6.1@5.114,34.902 5.337,34.902 5.655,34.584 U1.6@7.001,34.584
NetD1_1: D1.1 R5.1 U1.15 | length 2.3
  Bottom Layer w0.635: D1.1@23.794,24.262 23.926,24.13 R5.1@26.03,24.13
  other v1: 21.895,23.571 21.906,24.841 18.393,29.517 17.522,29.53
NetD1_2: D1.2 R7.1 | length 1.8
  Bottom Layer w0.635: D1.2@23.794,21.712 23.794,20.377 R7.1@24.156,20.015
NetD2_1: D2.1 R9.1 U1.10
  other v1: 24.294,34.417 24.308,35.331 17.45,35.839 18.288,35.839
NetD2_2: D2.2 R8.1
NetD3_1: D3.1 T1.4 | length 2.7
  Top Layer w0.63: T1.4@16.596,15.185 17.486,16.076 v1(17.486,16.388)
  Bottom Layer w0.635: v1(17.486,16.388) 17.486,16.81 D3.1@17.961,17.285
NetD3_2: D3.2 T1.6 | length 2.7
  Top Layer w0.63: T1.6@16.596,21.285 17.486,20.395 v1(17.486,20.071)
  Bottom Layer w0.635: v1(17.486,20.071) 17.486,19.66 D3.2@17.961,19.185
NetD4_1: D4.1 T2.4 | length 2.7
  Top Layer w0.63: T2.4@16.569,42.126 17.444,43.001 v1(17.444,43.352)
  Bottom Layer w0.635: v1(17.444,43.352) 17.444,43.699 D4.1@17.978,44.233
NetD4_2: D4.2 T2.6 | length 2.7
  Top Layer w0.63: T2.6@16.569,48.226 17.463,47.333 v1(17.463,47.027)
  Bottom Layer w0.635: v1(17.463,47.027) 17.463,46.648 D4.2@17.978,46.133
NetJ1_1: J1.1 R4.1 | length 23.1
  Bottom Layer w0.635: J1.1@2.134,4.293 1.778,4.648 1.778,25.194 2.621,26.037 R4.1@3.521,26.037
NetJ1_2: J1.2 R6.1 | length 31.2
  Bottom Layer w0.508: R6.1@3.481,27.597 R6.1@3.527,27.643
  Bottom Layer w0.635: R6.1@3.527,27.643 2.295,27.643 0.713,26.061 0.713,3.2 1.145,2.769 3.277,2.769 4.674,4.166 J1.2@4.674,4.293
NetJ1_3: J1.3 R3.2 U1.5 | length 43.1
  Top Layer w0.63: v1(1.422,31.547) 0.71,30.835 0.71,3.203 1.145,2.769 5.715,2.769
  Top Layer w0.635: 5.715,2.769 5.715,2.794 J1.3@7.214,4.293
  Bottom Layer w0.635: v1(1.422,31.547) 2.352,32.476 R3.2@3.076,32.476 3.076,33.378 3.381,33.683 5.344,33.683 5.694,33.332 6.984,33.332 U1.5@7.001,33.314
NetL1_1: L1.1 R5.2 R7.2 | length 2.1
  Bottom Layer w0.635: R5.2@26.03,22.098 26.188,21.94 R7.2@26.188,20.015
NetL2_1: L2.1 R8.2 R9.2
NetR12_1: R12.1 R13.2 U3.2 | length 4.3
  Bottom Layer w0.635: U3.2@25.359,14.357 R12.1@25.359,15.623 ; R12.1@25.359,15.725 R12.1@25.324,15.761 ; R13.2@26.899,15.303 R13.2@26.441,15.761 ; R12.1@25.324,15.761 R13.2@26.441,15.761 ; R12.1@25.324,15.761 R12.1@25.286,15.799 26.403,15.799 R13.2@26.441,15.761
NetR15_1: R15.1 R16.2 U5.2 | length 3.1
  Bottom Layer w0.635: R16.2@24.232,48.781 25.409,48.781 U5.2@25.695,49.067 25.695,47.941 R15.1@25.945,47.691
